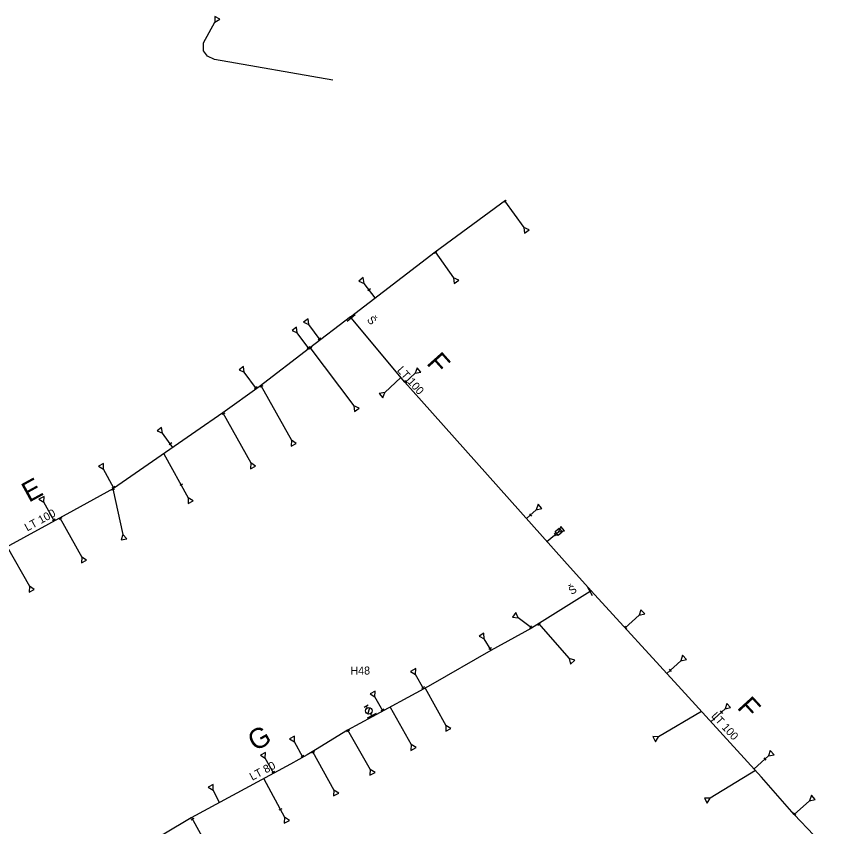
# Model space of a CAD drawing. Extents: x -574467 to -573664, y -1191210 to -1190404.
# Drawn here: x -574095.2 to -573889.4, y -1190606.2 to -1190403.8 of the extents above; entities that cross this region are included whole.
import ezdxf

# ---------------------------------------------------------------- set-up
doc = ezdxf.new("R2010")
doc.units = 0
for name, color, linetype in [('Vrstva 1', 7, 'Continuous'), ('Vrstva 12', 7, 'Continuous'), ('Vrstva 15', 7, 'Continuous'), ('Vrstva 25', 7, 'Continuous'), ('Vrstva 28', 7, 'Continuous'), ('Vrstva 29', 7, 'Continuous'), ('Vrstva 35', 7, 'Continuous')]:
    doc.layers.add(name, color=color, linetype=linetype)

# ---------------------------------------------------------------- blocks, each defined once
blk = doc.blocks.new('160')
at = {"layer": 'Vrstva 1'}
blk.add_circle((0, 0), 0.0458, dxfattribs=at)
blk = doc.blocks.new('147')
at = {"layer": 'Vrstva 1'}
blk.add_line((0, 1.27), (0, -1.27), dxfattribs=at)
blk = doc.blocks.new('133')
at = {"layer": 'Vrstva 1'}
for p, q in [((0.28, 0), (0, 0)), ((0.54, 0.58), (1.7, -0.58)), ((1.94, 0), (2.52, 0)), ((2.52, 0.58), (2.52, -0.58))]:
    blk.add_line(p, q, dxfattribs=at)
blk.add_circle((1.105, 0.003), 0.825, dxfattribs=at)
blk = doc.blocks.new('150')
at = {"layer": 'Vrstva 1'}
blk.add_line((0, 1.27), (0, -1.27), dxfattribs=at)
blk = doc.blocks.new('151')
at = {"layer": 'Vrstva 1'}
blk.add_line((0, 0.4), (0, -0.4), dxfattribs=at)
blk = doc.blocks.new('130')
at = {"layer": 'Vrstva 1'}
for p, q in [((1.25, 0.72), (0, 0)), ((0, 0), (1.25, -0.72)), ((1.25, -0.72), (1.25, 0.72))]:
    blk.add_line(p, q, dxfattribs=at)
blk = doc.blocks.new('171')
at = {"layer": 'Vrstva 1'}
blk.add_lwpolyline([(-0.68, 0.61), (0.67, 0.61), (0.67, -0.62), (-0.68, -0.62), (-0.68, 0.61)], dxfattribs=at)

msp = doc.modelspace()

# ---------------------------------------------------------------- linework, layer by layer
at = {"layer": 'Vrstva 12'}
for p, q in [((-573972.881, -1190449.81), (-573973.483, -1190450.231)), ((-573973.276, -1190449.833), (-573968.488, -1190456.524)), ((-573990.651, -1190462.604), (-573986.022, -1190469.072)), ((-574005.609, -1190474.122), (-574008.402, -1190470.495)), ((-574019.364, -1190484.603), (-574022.227, -1190480.751)), ((-574022.194, -1190486.743), (-574025.073, -1190482.865)), ((-574021.926, -1190486.539), (-574010.946, -1190501.073)), ((-574035.257, -1190496.808), (-574038.314, -1190492.698)), ((-573999.181, -1190494.042), (-574003.23, -1190497.72)), ((-573998.167, -1190495.255), (-573995.601, -1190492.963)), ((-574034.196, -1190496.022), (-574026.566, -1190509.706)), ((-574043.695, -1190502.866), (-574036.716, -1190515.367)), ((-574056.144, -1190511.473), (-574058.79, -1190507.9)), ((-574058.441, -1190513.061), (-574052.305, -1190524.068)), ((-574070.898, -1190521.673), (-574073.528, -1190516.941)), ((-574071.206, -1190521.858), (-574068.655, -1190533.218)), ((-574085.791, -1190529.836), (-574088.375, -1190525.155)), ((-573967.837, -1190529.219), (-573965.384, -1190527.063)), ((-574084.409, -1190529.08), (-574078.947, -1190538.882)), ((-573962.713, -1190534.957), (-573959.787, -1190532.563)), ((-574097.585, -1190536.287), (-574092.021, -1190546.188)), ((-573943.195, -1190556.594), (-573939.709, -1190553.408)), ((-573966.553, -1190556.582), (-573969.884, -1190554.055)), ((-573964.837, -1190555.509), (-573957.128, -1190564.191)), ((-573976.683, -1190562.166), (-573978.412, -1190559.345)), ((-573932.784, -1190567.983), (-573929.288, -1190564.805)), ((-573993.504, -1190571.849), (-573995.532, -1190568.197)), ((-573993.165, -1190571.656), (-573987.937, -1190580.94)), ((-574003.717, -1190577.341), (-574005.672, -1190573.831)), ((-574001.878, -1190576.352), (-573996.629, -1190585.735)), ((-573924.088, -1190577.496), (-573934.82, -1190583.771)), ((-573921.775, -1190580.027), (-573918.227, -1190576.803)), ((-574012.549, -1190582.091), (-574006.897, -1190591.956)), ((-574023.678, -1190588.873), (-574025.806, -1190585.078)), ((-574021.285, -1190587.46), (-574015.948, -1190597.086)), ((-573910.984, -1190591.832), (-573907.392, -1190588.566)), ((-574030.96, -1190592.935), (-574033.07, -1190589.121)), ((-573910.608, -1190592.243), (-573921.937, -1190599.113)), ((-574033.45, -1190594.272), (-574028.279, -1190603.899)), ((-574044.496, -1190600.204), (-574046.137, -1190597.157)), ((-573900.955, -1190603.228), (-573897.08, -1190599.77)), ((-574051.539, -1190603.986), (-574046.055, -1190613.771))]:
    msp.add_line(p, q, dxfattribs=at)
msp.add_lwpolyline([(-574016.164, -1190419.723), (-574045.785, -1190414.518), (-574047.501, -1190413.746), (-574048.53, -1190412.372), (-574048.53, -1190410.398), (-574045.699, -1190405.247)], dxfattribs=at)
at = {"layer": 'Vrstva 15'}
for p, q in [((-574011.613, -1190479.129), (-574011.808, -1190478.895)), ((-573951.697, -1190547.293), (-573951.945, -1190547.448))]:
    msp.add_line(p, q, dxfattribs=at)
for points in [[(-574011.808, -1190478.895), (-573990.652, -1190462.605), (-573973.068, -1190449.68)], [(-574011.808, -1190478.895), (-574022.069, -1190486.647), (-574034.639, -1190496.364), (-574043.695, -1190502.866), (-574050.388, -1190507.493), (-574071.014, -1190521.753), (-574081.02, -1190527.226), (-574137.249, -1190557.982), (-574164.872, -1190573.251), (-574169.864, -1190576.01), (-574171.768, -1190577.11), (-574173.02, -1190577.83)], [(-573951.697, -1190547.293), (-573958.304, -1190539.895), (-573994.045, -1190499.871), (-573998.203, -1190495.215), (-574011.613, -1190479.129)], [(-573951.945, -1190547.448), (-573966.611, -1190556.618), (-573976.732, -1190562.193), (-573991.762, -1190570.848), (-573993.455, -1190571.823), (-574006.385, -1190578.776), (-574012.553, -1190582.093), (-574020.568, -1190587.019), (-574022.653, -1190588.301), (-574026.786, -1190590.606), (-574030.918, -1190592.912), (-574051.57, -1190604.003), (-574065.696, -1190612.425), (-574079.8, -1190620.445), (-574081.027, -1190621.142), (-574115.994, -1190641.755), (-574117.43, -1190642.95), (-574120.356, -1190645.383)], [(-573889.37, -1190615.41), (-573891.12, -1190613.563), (-573900.955, -1190603.227), (-573909.109, -1190593.884), (-573929.133, -1190571.977), (-573951.697, -1190547.293)]]:
    msp.add_lwpolyline(points, dxfattribs=at)
at = {"layer": 'Vrstva 25'}
msp.add_line((-574006.388, -1190578.778), (-574006.663, -1190578.285), dxfattribs=at)

# ---------------------------------------------------------------- block references
at = {"layer": 'Vrstva 12'}
for name, p, xscale, yscale, rotation in [('130', (-574045.699, -1190405.247), 0.999999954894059, 0.9999999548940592, 60.999999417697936), ('130', (-573968.488, -1190456.524), 0.9999999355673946, 0.9999999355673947, -55.0000006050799), ('151', (-573990.513, -1190462.796), 0.9999999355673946, 0.9999999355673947, -55.0000006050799), ('130', (-574008.402, -1190470.495), 0.9999999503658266, 0.9999999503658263, 127.99999981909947), ('130', (-573986.022, -1190469.072), 0.9999999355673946, 0.9999999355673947, -55.0000006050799), ('151', (-574007.152, -1190472.119), 0.9999999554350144, 0.9999999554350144, -53.00000079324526), ('130', (-574022.227, -1190480.751), 0.9999999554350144, 0.9999999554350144, 126.99999920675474), ('130', (-574025.073, -1190482.865), 0.9999999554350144, 0.9999999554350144, 126.99999920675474), ('151', (-574019.51, -1190484.406), 0.9999999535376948, 0.9999999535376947, -53.99999865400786), ('151', (-574022.313, -1190486.582), 0.9999999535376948, 0.9999999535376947, -53.99999865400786), ('151', (-574021.782, -1190486.73), 0.9999999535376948, 0.9999999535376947, -53.99999865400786), ('130', (-574038.314, -1190492.698), 0.9999999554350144, 0.9999999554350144, 126.99999920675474), ('130', (-573995.601, -1190492.963), 0.9999999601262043, 0.9999999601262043, 41.999998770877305), ('151', (-574034.06, -1190496.266), 0.9999999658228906, 0.9999999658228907, -62.00000017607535), ('151', (-573997.928, -1190495.041), 0.9999999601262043, 0.9999999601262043, 41.999998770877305), ('151', (-574035.412, -1190496.6), 0.9999999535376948, 0.9999999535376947, -53.99999865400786), ('130', (-574003.23, -1190497.72), 0.9999999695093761, 0.9999999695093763, -138.9999986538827), ('130', (-574010.946, -1190501.073), 0.9999999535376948, 0.9999999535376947, -53.99999865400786), ('151', (-574043.565, -1190503.099), 0.9999999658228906, 0.9999999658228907, -62.00000017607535), ('130', (-574058.79, -1190507.9), 0.9999999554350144, 0.9999999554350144, 126.99999920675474), ('151', (-574056.783, -1190510.61), 0.9999999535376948, 0.9999999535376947, -53.99999865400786), ('130', (-574026.566, -1190509.706), 0.9999999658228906, 0.9999999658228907, -62.00000017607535), ('130', (-574073.528, -1190516.941), 0.999999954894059, 0.9999999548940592, 119.00000058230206), ('130', (-574036.716, -1190515.367), 0.9999999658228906, 0.9999999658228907, -62.00000017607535), ('151', (-574054.103, -1190520.843), 0.9999999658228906, 0.9999999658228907, -62.00000017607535), ('151', (-574071.149, -1190522.11), 0.999999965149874, 0.9999999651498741, -77.9999999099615), ('151', (-574071.029, -1190521.438), 0.9999999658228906, 0.9999999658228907, -62.00000017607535), ('130', (-574088.375, -1190525.155), 0.999999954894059, 0.9999999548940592, 119.00000058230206), ('130', (-574052.305, -1190524.068), 0.9999999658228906, 0.9999999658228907, -62.00000017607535), ('130', (-573965.384, -1190527.063), 0.9999999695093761, 0.9999999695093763, 41.000001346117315), ('151', (-574084.292, -1190529.289), 0.9999999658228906, 0.9999999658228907, -62.00000017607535), ('151', (-573966.839, -1190528.342), 0.9999999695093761, 0.9999999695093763, 41.000001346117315), ('151', (-574085.918, -1190529.605), 0.9999999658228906, 0.9999999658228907, -62.00000017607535), ('130', (-574068.655, -1190533.218), 0.999999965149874, 0.9999999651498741, -77.9999999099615), ('151', (-573960.623, -1190533.247), 0.9999999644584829, 0.999999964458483, 39.000001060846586), ('171', (-573959.787, -1190532.563), 0.9999999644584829, 0.999999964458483, 39.000001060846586), ('130', (-573959.787, -1190532.563), 0.9999999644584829, 0.999999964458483, 39.000001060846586), ('130', (-574078.947, -1190538.882), 0.9999999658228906, 0.9999999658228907, -62.00000017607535), ('130', (-574092.021, -1190546.188), 0.9999999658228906, 0.9999999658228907, -62.00000017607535), ('130', (-573969.884, -1190554.055), 0.9999999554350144, 0.9999999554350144, 143.00000079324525), ('130', (-573939.709, -1190553.408), 0.9999999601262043, 0.9999999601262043, 41.999998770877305), ('151', (-573964.673, -1190555.694), 0.9999999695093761, 0.9999999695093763, -48.99999865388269), ('130', (-573978.412, -1190559.345), 0.9999999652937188, 0.9999999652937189, 121.99999738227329), ('151', (-573966.797, -1190556.397), 0.9999999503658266, 0.9999999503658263, -37.999999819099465), ('151', (-573943.067, -1190556.477), 0.9999999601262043, 0.9999999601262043, 41.999998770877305), ('151', (-573976.911, -1190561.794), 0.9999999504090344, 0.9999999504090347, -58.99999841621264), ('130', (-573957.128, -1190564.191), 0.9999999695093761, 0.9999999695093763, -48.99999865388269), ('130', (-573929.288, -1190564.805), 0.9999999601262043, 0.9999999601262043, 41.999998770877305), ('130', (-573995.532, -1190568.197), 0.999999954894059, 0.9999999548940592, 119.00000058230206), ('151', (-573931.934, -1190567.21), 0.9999999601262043, 0.9999999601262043, 41.999998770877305), ('151', (-573993.697, -1190571.501), 0.9999999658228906, 0.9999999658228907, -62.00000017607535), ('130', (-574005.672, -1190573.831), 0.999999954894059, 0.9999999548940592, 119.00000058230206), ('130', (-573918.227, -1190576.803), 0.9999999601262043, 0.9999999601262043, 41.999998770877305), ('151', (-574003.846, -1190577.109), 0.9999999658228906, 0.9999999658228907, -62.00000017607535), ('151', (-573919.138, -1190577.631), 0.9999999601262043, 0.9999999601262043, 41.999998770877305), ('151', (-574012.398, -1190582.355), 0.999999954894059, 0.9999999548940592, -60.999999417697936), ('130', (-573987.937, -1190580.94), 0.9999999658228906, 0.9999999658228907, -62.00000017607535), ('130', (-574025.806, -1190585.078), 0.999999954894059, 0.9999999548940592, 119.00000058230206), ('130', (-573934.82, -1190583.771), 1.0037041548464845, 1.0037041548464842, -150.62079141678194), ('130', (-573996.629, -1190585.735), 0.9999999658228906, 0.9999999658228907, -62.00000017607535), ('130', (-574033.07, -1190589.121), 0.999999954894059, 0.9999999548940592, 119.00000058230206), ('151', (-574023.787, -1190588.679), 0.9999999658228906, 0.9999999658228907, -62.00000017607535), ('151', (-574021.15, -1190587.704), 0.9999999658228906, 0.9999999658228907, -62.00000017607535), ('130', (-573907.392, -1190588.566), 0.9999999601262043, 0.9999999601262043, 41.999998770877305), ('151', (-573908.262, -1190589.357), 0.9999999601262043, 0.9999999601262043, 41.999998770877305), ('151', (-574031.119, -1190592.647), 0.9999999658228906, 0.9999999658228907, -62.00000017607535), ('130', (-574006.897, -1190591.956), 0.999999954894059, 0.9999999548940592, -60.999999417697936), ('130', (-574046.137, -1190597.157), 0.9999999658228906, 0.9999999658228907, 117.99999982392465), ('130', (-574015.948, -1190597.086), 0.9999999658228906, 0.9999999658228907, -62.00000017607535), ('130', (-573921.937, -1190599.113), 0.9999999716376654, 0.9999999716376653, -150.00000103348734), ('130', (-573897.08, -1190599.77), 0.9999999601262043, 0.9999999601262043, 41.999998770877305), ('151', (-574029.328, -1190601.946), 0.999999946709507, 0.999999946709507, -62.999999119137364), ('151', (-573900.815, -1190603.103), 0.9999999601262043, 0.9999999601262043, 41.999998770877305), ('151', (-574051.31, -1190604.395), 0.9999999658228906, 0.9999999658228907, -62.00000017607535), ('130', (-574028.279, -1190603.899), 0.999999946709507, 0.999999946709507, -62.999999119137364)]:
    msp.add_blockref(name, p, dxfattribs=dict(at, xscale=xscale, yscale=yscale, rotation=rotation))
at = {"layer": 'Vrstva 25'}
for name, p, xscale, yscale, rotation in [('133', (-574006.663, -1190578.285), 0.999999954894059, 0.9999999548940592, 119.00000058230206), ('150', (-574006.525, -1190578.531), 0.9999999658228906, 0.9999999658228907, -62.00000017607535)]:
    msp.add_blockref(name, p, dxfattribs=dict(at, xscale=xscale, yscale=yscale, rotation=rotation))
at = {"layer": 'Vrstva 29'}
for name, p, xscale, yscale, rotation in [('147', (-574011.613, -1190479.129), 0.9999999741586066, 0.9999999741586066, 129.99999870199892), ('160', (-574011.808, -1190478.895), 0.9999999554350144, 0.9999999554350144, 36.99999920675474), ('147', (-573951.945, -1190547.448), 0.9999999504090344, 0.9999999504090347, -148.99999841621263), ('160', (-573951.697, -1190547.293), 1.0092050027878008, 1.0092050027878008, 168.88308178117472)]:
    msp.add_blockref(name, p, dxfattribs=dict(at, xscale=xscale, yscale=yscale, rotation=rotation))

# ---------------------------------------------------------------- texts
at = {"layer": 'Vrstva 25'}
msp.add_text('H48', height=2, dxfattribs=at).set_placement((-574011.813, -1190568.235))
at = {"layer": 'Vrstva 28'}
for rotation, p in [(310.32, (-574007.808, -1190479.68)), (31.52, (-573956.564, -1190548.377))]:
    msp.add_text('Š', height=2, rotation=rotation, dxfattribs=at).set_placement(p)
at = {"layer": 'Vrstva 35'}
for s, height, rotation, p in [('F', 5, 311.77, (-573992.986, -1190490.538)), ('LT 100', 2, 311.77, (-574000.281, -1190492.287)), ('E', 5, 28.68, (-574092.14, -1190525.333)), ('LT 100', 2, 28.68, (-574092.549, -1190532.503)), ('F', 5, 312.43, (-573915.414, -1190576.606)), ('LT 100', 2, 312.43, (-573921.785, -1190578.678)), ('G', 5, 29.16, (-574035.644, -1190587.535)), ('LT 80', 2, 28.24, (-574036.336, -1190594.8))]:
    msp.add_text(s, height=height, rotation=rotation, dxfattribs=at).set_placement(p)

doc.saveas('drawing.dxf')
